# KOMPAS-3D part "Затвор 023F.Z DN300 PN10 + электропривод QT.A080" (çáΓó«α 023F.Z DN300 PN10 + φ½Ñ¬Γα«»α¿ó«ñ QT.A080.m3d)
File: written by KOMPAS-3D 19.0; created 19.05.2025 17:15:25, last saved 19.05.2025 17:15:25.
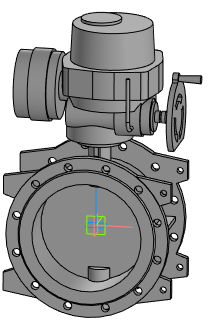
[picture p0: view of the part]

Document properties: Полное имя файла: Затвор 023F.Z DN300 PN10 + электропривод QT.A080.a3d

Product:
- Part/product: Затвор 023F.Z DN300 PN10 + электропривод QT.A080
    Масса: 220.759

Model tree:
1. Операция без истории:1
